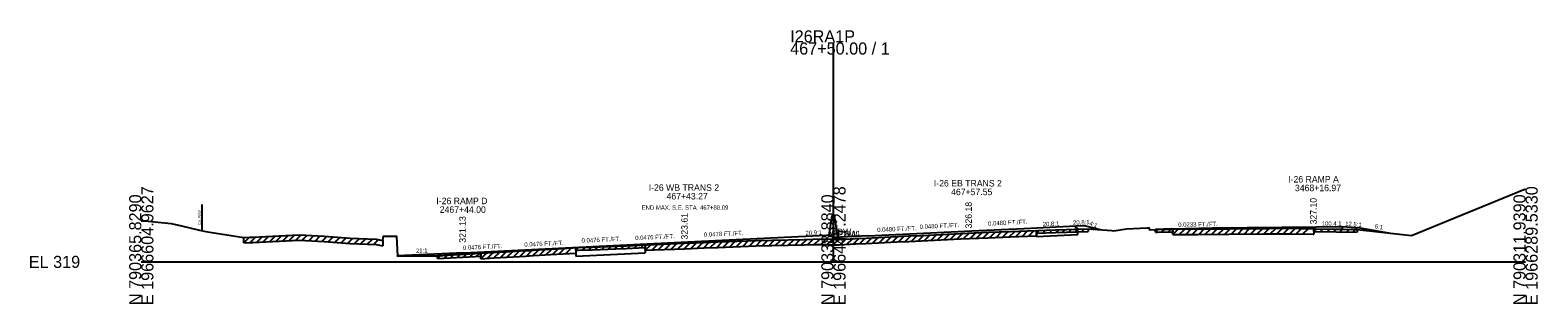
# Model space of a CAD drawing. Extents: x -44 to 4323, y -10 to 9601.
# Drawn here: x 3974.3 to 4322.8, y 5990.3 to 6053.6 of the extents above; entities that cross this region are included whole.
import ezdxf

# ---------------------------------------------------------------- set-up
doc = ezdxf.new("R2010")
doc.units = 0
for name, color, linetype in [('1', 7, 'Continuous'), ('DateStamp', 7, 'Continuous'), ('NotForConst', 7, 'Continuous'), ('QCQA', 7, 'Continuous'), ('RD_SHT_Bndy', 7, 'Continuous'), ('RD_SHT_Iplotshp', 7, 'Continuous'), ('RD_SHT_TX', 7, 'Continuous'), ('RD_XS_ExGround', 7, 'Continuous'), ('RD_XS_MatchLine', 7, 'Continuous'), ('RD_XS_MedBWall', 7, 'Continuous'), ('RD_XS_Misc_Line', 7, 'Continuous'), ('RD_XS_Pave', 7, 'Continuous'), ('RD_XS_PaveOvlay', 7, 'Continuous'), ('RD_XS_PaveShd', 7, 'Continuous'), ('RD_XS_TX_Elev_PR', 7, 'Continuous'), ('RD_XS_TX_Profile', 7, 'Continuous'), ('RD_XS_TX_ShdSlope', 7, 'Continuous'), ('RD_XS_TX_Slope', 7, 'Continuous'), ('seal', 7, 'Continuous'), ('TR SN EXTRUDED PANEL SIGNS - GROUND MOUNTED', 7, 'Continuous')]:
    doc.layers.add(name, color=color, linetype=linetype)

msp = doc.modelspace()

# ---------------------------------------------------------------- linework, layer by layer
at = {"layer": 'DateStamp'}
msp.add_lwpolyline([(4000, 6009.47), (4000.81, 6009.46), (4006.14, 6008.97), (4006.93, 6008.89), (4009.26, 6008.36), (4013.47, 6007.37), (4014.92, 6007.03), (4015.83, 6006.91), (4023.69, 6005.65), (4025.09, 6005.7), (4025.8, 6005.73), (4028.82, 6005.9), (4036.52, 6006.28), (4042.28, 6005.93), (4048.28, 6005.48), (4054.31, 6005.25), (4055.84, 6004.97), (4055.97, 6005.95), (4056.55, 6005.95), (4058.97, 6005.95), (4059.24, 6001.33), (4066.69, 6001.4), (4068.51, 6001.42), (4077.18, 6001.91), (4081.57, 6002.17), (4088.89, 6002.6), (4089.67, 6002.65), (4090.68, 6002.71), (4094.59, 6002.93), (4101.09, 6003.3), (4104.25, 6003.43), (4109.73, 6003.66), (4112.08, 6003.75), (4118.56, 6004.01), (4125.61, 6004.3), (4130.09, 6004.49), (4133.29, 6004.61), (4142.15, 6004.93), (4145.79, 6005.01), (4153.2, 6005.2), (4155.24, 6005.24), (4158.57, 6005.3), (4160.22, 6005.23), (4161.32, 6005.2), (4165.14, 6005.4), (4167.58, 6005.52), (4174.64, 6005.86), (4177.4, 6005.99), (4180.34, 6006.14), (4189.37, 6006.6), (4195.68, 6006.84), (4200.88, 6007.02), (4211.32, 6007.41), (4218.91, 6007.67), (4224.37, 6007.25), (4224.84, 6007.22), (4227.75, 6007.62), (4232.51, 6007.85), (4232.95, 6007.88), (4233.05, 6007.43), (4234.45, 6007.52), (4234.92, 6007.53), (4238.34, 6007.58), (4244.23, 6007.62), (4251.44, 6007.68), (4259.7, 6007.72), (4260.04, 6007.73), (4260.79, 6007.73), (4265.4, 6007.77), (4270.87, 6007.65), (4271.41, 6007.64), (4281.1, 6007.46), (4286.01, 6006.96), (4293.61, 6006.1), (4320, 6016.91)], dxfattribs=at)
at = {"layer": 'NotForConst'}
for p, q in [((4023.69, 6004.4), (4024.99, 6005.7)), ((4025.19, 6004.46), (4026.51, 6005.77)), ((4026.69, 6004.53), (4028.01, 6005.85)), ((4028.19, 6004.61), (4029.51, 6005.93)), ((4029.69, 6004.69), (4031.01, 6006.01)), ((4031.19, 6004.77), (4032.51, 6006.08)), ((4032.69, 6004.84), (4034.01, 6006.16)), ((4034.2, 6004.92), (4035.51, 6006.23)), ((4035.7, 6004.99), (4036.96, 6006.26)), ((4037.2, 6004.99), (4038.38, 6006.17)), ((4038.7, 6004.9), (4039.88, 6006.08)), ((4040.2, 6004.81), (4041.38, 6005.99)), ((4041.7, 6004.72), (4042.87, 6005.89)), ((4043.2, 6004.61), (4044.36, 6005.78)), ((4044.7, 6004.5), (4045.86, 6005.66)), ((4046.2, 6004.39), (4047.36, 6005.55)), ((4047.7, 6004.27), (4048.88, 6005.46)), ((4049.2, 6004.19), (4050.41, 6005.4)), ((4050.7, 6004.14), (4051.91, 6005.34)), ((4052.2, 6004.08), (4053.41, 6005.28)), ((4154.04, 6003.96), (4155.32, 6005.24)), ((4155.54, 6003.99), (4156.82, 6005.27)), ((4157.05, 6004.02), (4158.32, 6005.3)), ((4158.55, 6004.05), (4159.75, 6005.25)), ((4161.55, 6003.96), (4162.87, 6005.28)), ((4163.05, 6004.04), (4164.38, 6005.36)), ((4164.55, 6004.12), (4165.87, 6005.44)), ((4166.06, 6004.2), (4167.37, 6005.51)), ((4167.56, 6004.27), (4168.87, 6005.59)), ((4169.06, 6004.34), (4170.38, 6005.66)), ((4170.56, 6004.42), (4171.88, 6005.73)), ((4172.06, 6004.49), (4173.38, 6005.8)), ((4173.57, 6004.56), (4174.88, 6005.87)), ((4175.07, 6004.63), (4176.38, 6005.95)), ((4176.57, 6004.71), (4177.89, 6006.02)), ((4178.07, 6004.78), (4179.39, 6006.1)), ((4179.57, 6004.86), (4180.89, 6006.17)), ((4181.08, 6004.93), (4182.39, 6006.25)), ((4182.58, 6005.01), (4183.9, 6006.32)), ((4184.08, 6005.08), (4185.4, 6006.4)), ((4185.58, 6005.16), (4186.9, 6006.48)), ((4187.08, 6005.24), (4188.4, 6006.55)), ((4188.58, 6005.31), (4189.9, 6006.62)), ((4190.09, 6005.38), (4191.39, 6006.68)), ((4191.59, 6005.43), (4192.89, 6006.73)), ((4193.09, 6005.49), (4194.39, 6006.79)), ((4194.59, 6005.55), (4195.89, 6006.84)), ((4196.09, 6005.6), (4197.39, 6006.9)), ((4197.6, 6005.65), (4198.89, 6006.95)), ((4199.1, 6005.71), (4200.4, 6007)), ((4200.6, 6005.76), (4201.9, 6007.06)), ((4202.1, 6005.82), (4203.4, 6007.11)), ((4203.6, 6005.87), (4204.9, 6007.17)), ((4205.11, 6005.93), (4206.4, 6007.23)), ((4206.91, 6006.62), (4207.56, 6007.27)), ((4208.41, 6006.67), (4209.06, 6007.32)), ((4209.92, 6006.73), (4210.57, 6007.38)), ((4211.42, 6006.78), (4212.07, 6007.43)), ((4212.92, 6006.84), (4213.57, 6007.48)), ((4214.42, 6006.89), (4215.07, 6007.54)), ((4215.92, 6006.94), (4216.57, 6007.59)), ((4217.43, 6006.99), (4218.07, 6007.64)), ((4234.45, 6006.9), (4235.08, 6007.53)), ((4235.95, 6006.92), (4236.58, 6007.56)), ((4237.45, 6006.95), (4238.09, 6007.58)), ((4238.45, 6006.34), (4239.71, 6007.59)), ((4239.95, 6006.34), (4241.21, 6007.6)), ((4241.45, 6006.35), (4242.71, 6007.61)), ((4242.95, 6006.36), (4244.21, 6007.62)), ((4244.45, 6006.37), (4245.71, 6007.63)), ((4245.96, 6006.39), (4247.22, 6007.65)), ((4247.46, 6006.4), (4248.72, 6007.66)), ((4248.96, 6006.41), (4250.22, 6007.67)), ((4250.46, 6006.42), (4251.72, 6007.68)), ((4251.96, 6006.43), (4253.22, 6007.69)), ((4253.46, 6006.44), (4254.72, 6007.7)), ((4254.97, 6006.45), (4256.22, 6007.71)), ((4256.47, 6006.46), (4257.73, 6007.71)), ((4257.97, 6006.47), (4259.23, 6007.72)), ((4259.47, 6006.47), (4260.73, 6007.73)), ((4260.97, 6006.48), (4262.24, 6007.74)), ((4262.48, 6006.5), (4263.74, 6007.76)), ((4263.98, 6006.51), (4265.24, 6007.77)), ((4265.48, 6006.52), (4266.71, 6007.74)), ((4266.98, 6006.49), (4268.21, 6007.71)), ((4268.48, 6006.46), (4269.71, 6007.68)), ((4271.09, 6007.03), (4271.71, 6007.64)), ((4272.59, 6007), (4273.21, 6007.61)), ((4274.1, 6006.97), (4274.71, 6007.58)), ((4275.6, 6006.94), (4276.21, 6007.56)), ((4277.1, 6006.91), (4277.71, 6007.53)), ((4278.6, 6006.89), (4279.22, 6007.5)), ((4280.1, 6006.86), (4280.72, 6007.47)), ((4053.7, 6004.02), (4054.83, 6005.15)), ((4074.52, 6001.13), (4075.18, 6001.8)), ((4076.02, 6001.22), (4076.68, 6001.88)), ((4077.52, 6001.3), (4078.18, 6001.97)), ((4078.52, 6000.74), (4079.85, 6002.07)), ((4080.02, 6000.83), (4081.35, 6002.16)), ((4081.52, 6000.92), (4082.85, 6002.24)), ((4083.03, 6001.01), (4084.36, 6002.33)), ((4084.53, 6001.09), (4085.86, 6002.42)), ((4086.03, 6001.18), (4087.36, 6002.51)), ((4087.53, 6001.27), (4088.86, 6002.6)), ((4089.03, 6001.36), (4090.36, 6002.69)), ((4090.54, 6001.45), (4091.86, 6002.77)), ((4092.04, 6001.53), (4093.36, 6002.86)), ((4093.54, 6001.62), (4094.87, 6002.95)), ((4095.04, 6001.71), (4096.37, 6003.03)), ((4096.54, 6001.79), (4097.87, 6003.12)), ((4098.04, 6001.88), (4099.37, 6003.2)), ((4100.43, 6002.64), (4101.09, 6003.3)), ((4101.93, 6002.71), (4102.58, 6003.36)), ((4103.43, 6002.77), (4104.09, 6003.43)), ((4104.94, 6002.84), (4105.59, 6003.49)), ((4106.44, 6002.9), (4107.09, 6003.55)), ((4107.94, 6002.96), (4108.59, 6003.61)), ((4109.44, 6003.02), (4110.09, 6003.67)), ((4110.94, 6003.08), (4111.59, 6003.73)), ((4112.44, 6003.14), (4113.1, 6003.79)), ((4113.95, 6003.2), (4114.6, 6003.85)), ((4115.45, 6003.26), (4116.1, 6003.91)), ((4116.49, 6002.68), (4117.8, 6003.98)), ((4118, 6002.74), (4119.3, 6004.04)), ((4119.5, 6002.8), (4120.8, 6004.1)), ((4121, 6002.86), (4122.31, 6004.16)), ((4122.5, 6002.92), (4123.81, 6004.23)), ((4124, 6002.99), (4125.31, 6004.29)), ((4125.51, 6003.05), (4126.81, 6004.35)), ((4127.01, 6003.11), (4128.31, 6004.42)), ((4128.51, 6003.18), (4129.82, 6004.48)), ((4130.01, 6003.24), (4131.31, 6004.54)), ((4131.51, 6003.3), (4132.81, 6004.6)), ((4133.02, 6003.35), (4134.31, 6004.65)), ((4134.52, 6003.41), (4135.81, 6004.7)), ((4136.02, 6003.46), (4137.32, 6004.76)), ((4137.52, 6003.51), (4138.82, 6004.81)), ((4139.02, 6003.57), (4140.32, 6004.86)), ((4140.52, 6003.62), (4141.82, 6004.92)), ((4142.03, 6003.67), (4143.31, 6004.96)), ((4143.53, 6003.71), (4144.81, 6004.99)), ((4145.03, 6003.75), (4146.31, 6005.03)), ((4146.53, 6003.78), (4147.82, 6005.06)), ((4148.03, 6003.82), (4149.32, 6005.1)), ((4149.54, 6003.86), (4150.82, 6005.14)), ((4151.04, 6003.89), (4152.32, 6005.18)), ((4152.54, 6003.93), (4153.82, 6005.21)), ((4160.05, 6003.99), (4161.26, 6005.2)), ((4068.51, 6000.8), (4069.17, 6001.46)), ((4070.01, 6000.88), (4070.67, 6001.54)), ((4071.51, 6000.96), (4072.17, 6001.63)), ((4073.01, 6001.05), (4073.68, 6001.71))]:
    msp.add_line(p, q, dxfattribs=at)
at = {"layer": 'QCQA'}
for p, q in [((4153.2, 6005.2), (4155.24, 6005.24)), ((4155.24, 6005.24), (4158.57, 6005.3)), ((4158.57, 6005.3), (4160.22, 6005.23)), ((4160.22, 6005.23), (4161.32, 6005.2)), ((4161.32, 6005.2), (4165.14, 6005.4)), ((4165.14, 6005.4), (4167.58, 6005.52)), ((4167.58, 6005.52), (4174.64, 6005.86)), ((4174.64, 6005.86), (4177.4, 6005.99)), ((4177.4, 6005.99), (4180.34, 6006.14)), ((4180.34, 6006.14), (4189.37, 6006.6)), ((4189.37, 6006.6), (4195.68, 6006.84)), ((4195.68, 6006.84), (4200.88, 6007.02)), ((4200.88, 6007.02), (4206.91, 6007.24)), ((4238.45, 6007.59), (4234.45, 6007.52)), ((4238.45, 6007.59), (4244.23, 6007.62)), ((4244.23, 6007.62), (4251.44, 6007.68)), ((4251.44, 6007.68), (4259.7, 6007.72)), ((4259.7, 6007.72), (4260.04, 6007.73)), ((4260.04, 6007.73), (4260.79, 6007.73)), ((4260.79, 6007.73), (4265.4, 6007.77)), ((4265.4, 6007.77), (4270.87, 6007.65)), ((4270.87, 6007.65), (4271.09, 6007.65)), ((4271.09, 6007.65), (4277.71, 6007.53)), ((4075.18, 6001.8), (4068.51, 6001.42)), ((4079.38, 6002.04), (4075.18, 6001.8)), ((4088.89, 6002.6), (4079.38, 6002.04)), ((4088.89, 6002.6), (4089.67, 6002.65)), ((4089.67, 6002.65), (4090.68, 6002.71)), ((4100.43, 6003.26), (4090.68, 6002.71)), ((4116.49, 6003.93), (4100.43, 6003.26)), ((4100.43, 6003.26), (4100.43, 6001.33)), ((4116.49, 6003.93), (4118.56, 6004.01)), ((4116.49, 6003.93), (4116.49, 6002.1)), ((4118.56, 6004.01), (4125.61, 6004.3)), ((4125.61, 6004.3), (4130.09, 6004.49)), ((4130.09, 6004.49), (4133.29, 6004.61)), ((4133.29, 6004.61), (4142.15, 6004.93)), ((4142.15, 6004.93), (4145.79, 6005.01)), ((4145.79, 6005.01), (4153.2, 6005.2)), ((4068.51, 6001.42), (4059.24, 6001.33)), ((4059.24, 6001.33), (4059.24, 6001.4))]:
    msp.add_line(p, q, dxfattribs=at)
at = {"layer": 'RD_SHT_Bndy'}
for p, q in [((4160, 6000), (4160, 6050.73)), ((4000, 6000), (4160, 6000)), ((4160, 6000), (4320, 6000))]:
    msp.add_line(p, q, dxfattribs=at)
at = {"layer": 'RD_SHT_Iplotshp'}
for p, q in [((4023.69, 6004.4), (4023.69, 6005.65)), ((4180.34, 6004.89), (4189.37, 6005.35)), ((4189.37, 6005.35), (4195.68, 6005.59)), ((4195.68, 6005.59), (4200.88, 6005.77)), ((4200.88, 6005.77), (4206.91, 6005.99)), ((4206.91, 6007.24), (4206.91, 6005.99)), ((4206.91, 6006.62), (4206.91, 6007.24)), ((4206.91, 6006.62), (4211.32, 6006.78)), ((4211.32, 6006.78), (4218.91, 6007.04)), ((4218.91, 6007.67), (4218.91, 6007.04)), ((4234.45, 6006.9), (4234.45, 6007.52)), ((4234.45, 6006.9), (4234.92, 6006.91)), ((4234.92, 6006.91), (4238.34, 6006.96)), ((4238.34, 6006.96), (4238.45, 6006.96)), ((4238.45, 6006.34), (4238.45, 6007.59)), ((4238.45, 6007.59), (4238.45, 6006.96)), ((4238.45, 6006.34), (4244.23, 6006.37)), ((4244.23, 6006.37), (4251.44, 6006.43)), ((4251.44, 6006.43), (4259.7, 6006.47)), ((4259.7, 6006.47), (4260.04, 6006.48)), ((4260.04, 6006.48), (4260.79, 6006.48)), ((4260.79, 6006.48), (4265.4, 6006.52)), ((4265.4, 6006.52), (4270.87, 6006.4)), ((4270.87, 6006.4), (4271.09, 6006.4)), ((4271.09, 6007.65), (4271.09, 6006.4)), ((4271.09, 6007.03), (4271.09, 6007.65)), ((4271.09, 6007.03), (4271.41, 6007.02)), ((4271.41, 6007.02), (4281.1, 6006.84)), ((4281.1, 6007.46), (4281.1, 6006.84)), ((4023.69, 6004.4), (4025.09, 6004.45)), ((4025.09, 6004.45), (4025.8, 6004.48)), ((4025.8, 6004.48), (4028.82, 6004.65)), ((4028.82, 6004.65), (4036.52, 6005.03)), ((4036.52, 6005.03), (4042.28, 6004.68)), ((4042.28, 6004.68), (4048.28, 6004.23)), ((4048.28, 6004.23), (4054.31, 6004)), ((4054.31, 6004), (4055.84, 6003.72)), ((4055.84, 6004.97), (4055.84, 6003.72)), ((4078.52, 6000.74), (4078.52, 6001.99)), ((4078.52, 6001.99), (4078.52, 6001.36)), ((4094.59, 6001.68), (4100.43, 6002.01)), ((4100.43, 6003.26), (4100.43, 6002.01)), ((4100.43, 6002.64), (4100.43, 6003.26)), ((4100.43, 6002.64), (4101.09, 6002.68)), ((4101.09, 6002.68), (4104.25, 6002.81)), ((4104.25, 6002.81), (4109.73, 6003.03)), ((4109.73, 6003.03), (4112.08, 6003.13)), ((4112.08, 6003.13), (4116.49, 6003.3)), ((4116.49, 6002.68), (4116.49, 6003.93)), ((4116.49, 6003.93), (4116.49, 6003.3)), ((4116.49, 6002.68), (4118.56, 6002.76)), ((4118.56, 6002.76), (4125.61, 6003.05)), ((4125.61, 6003.05), (4130.09, 6003.24)), ((4130.09, 6003.24), (4133.29, 6003.36)), ((4133.29, 6003.36), (4142.15, 6003.68)), ((4142.15, 6003.68), (4145.79, 6003.76)), ((4145.79, 6003.76), (4153.2, 6003.95)), ((4153.2, 6003.95), (4155.24, 6003.99)), ((4155.24, 6003.99), (4158.57, 6004.05)), ((4158.57, 6004.05), (4160.22, 6003.98)), ((4160.22, 6003.98), (4161.32, 6003.95)), ((4161.32, 6003.95), (4165.14, 6004.15)), ((4165.14, 6004.15), (4167.58, 6004.27)), ((4167.58, 6004.27), (4174.64, 6004.61)), ((4174.64, 6004.61), (4177.4, 6004.74)), ((4177.4, 6004.74), (4180.34, 6004.89)), ((4068.51, 6000.8), (4068.51, 6001.42)), ((4068.51, 6000.8), (4077.18, 6001.28)), ((4077.18, 6001.28), (4078.52, 6001.36)), ((4078.52, 6000.74), (4081.57, 6000.92)), ((4081.57, 6000.92), (4088.89, 6001.35)), ((4088.89, 6001.35), (4089.67, 6001.4)), ((4089.67, 6001.4), (4090.68, 6001.46)), ((4090.68, 6001.46), (4094.59, 6001.68))]:
    msp.add_line(p, q, dxfattribs=at)
at = {"layer": 'RD_XS_Misc_Line'}
for p, q in [((4206.91, 6005.86), (4206.91, 6007.24)), ((4206.91, 6005.86), (4216.5, 6006.32)), ((4216, 6007.78), (4216, 6008.34)), ((4216, 6007.78), (4216.5, 6007.8)), ((4216.5, 6006.32), (4216.5, 6007.8)), ((4277.71, 6007.53), (4277.71, 6008.16)), ((4100.43, 6001.33), (4116.49, 6002.1))]:
    msp.add_line(p, q, dxfattribs=at)
at = {"layer": 'RD_XS_Pave'}
for p, q in [((4218, 6008.43), (4222, 6007.43)), ((4281.72, 6007.84), (4289.16, 6006.6))]:
    msp.add_line(p, q, dxfattribs=at)
at = {"layer": 'RD_XS_PaveOvlay'}
msp.add_line((4014, 6013.25), (4014, 6007.25), dxfattribs=at)
at = {"layer": 'RD_XS_PaveShd'}
for p, q in [((4216, 6008.34), (4218, 6008.43)), ((4277.71, 6008.16), (4281.72, 6007.84))]:
    msp.add_line(p, q, dxfattribs=at)
at = {"layer": 'RD_XS_TX_Elev_PR'}
for p, q in [((4150.31, 6005.76), (4160, 6006.22)), ((4160, 6006.22), (4160, 6005.65)), ((4168, 6006.03), (4160, 6005.65)), ((4204, 6007.76), (4216, 6008.34)), ((4238.14, 6007.64), (4234.45, 6007.52)), ((4271.7, 6008.1), (4277.71, 6008.16)), ((4074.59, 6002.13), (4059.24, 6001.4))]:
    msp.add_line(p, q, dxfattribs=at)
at = {"layer": 'RD_XS_TX_ShdSlope'}
for p, q in [((4159, 6006.17), (4159.67, 6010.72)), ((4160.33, 6010.72), (4159.67, 6010.72)), ((4160, 6010.72), (4159.67, 6010.72)), ((4160.33, 6010.15), (4160.33, 6010.72)), ((4161, 6005.7), (4160.33, 6010.15))]:
    msp.add_line(p, q, dxfattribs=at)
at = {"layer": 'RD_XS_TX_Slope'}
for p, q in [((4126.31, 6004.61), (4150.31, 6005.76)), ((4168, 6006.03), (4192, 6007.18)), ((4192, 6007.18), (4204, 6007.76)), ((4238.14, 6007.64), (4247.64, 6007.86)), ((4247.64, 6007.86), (4271.7, 6008.1)), ((4074.59, 6002.13), (4126.31, 6004.61))]:
    msp.add_line(p, q, dxfattribs=at)

# ---------------------------------------------------------------- texts
at = {"layer": '1'}
for s, p in [('I-26 RAMP A', (4265.13, 6018.35)), ('I-26 WB TRANS 2', (4117.3, 6016.43)), ('467+43.27', (4121.42, 6014.43)), ('I-26 EB TRANS 2', (4183.22, 6017.43)), ('467+57.55', (4187.2, 6015.43)), ('3468+16.97', (4266.69, 6016.35)), ('I-26 RAMP D', (4068.21, 6013.34)), ('2467+44.00', (4068.99, 6011.34))]:
    msp.add_text(s, height=1.5, dxfattribs=at).set_placement(p)
at = {"layer": 'RD_SHT_Bndy'}
for s, p in [('467+50.00 / 1', (4150, 6047.93)), ('I26RA1P', (4150, 6050.73)), ('EL 319', (3974, 5998.6))]:
    msp.add_text(s, height=2.8, dxfattribs=at).set_placement(p)
for s, p in [('E 1966604.9627', (4002.8, 5990)), ('E 1966447.2478', (4162.8, 5990)), ('E 1966289.5330', (4322.8, 5990)), ('N 790365.8290', (4000, 5990)), ('N 790338.8840', (4160, 5990)), ('N 790311.9390', (4320, 5990))]:
    msp.add_text(s, height=2.8, rotation=90, dxfattribs=at).set_placement(p)
at = {"layer": 'RD_SHT_TX'}
msp.add_text('324.24', height=1, rotation=90, dxfattribs=at).set_placement((4161, 6005.24))
at = {"layer": 'RD_XS_ExGround'}
for s, rotation, p in [('20.8:1', 2.7481, (4208.41, 6008.22)), ('20.9:1', 2.7384, (4153.57, 6006.16)), ('20.8:1', 2.7481, (4162.41, 6006.01)), ('21:1', 2.7234, (4063.51, 6002.05))]:
    msp.add_text(s, height=1, rotation=rotation, dxfattribs=at).set_placement(p)
at = {"layer": 'RD_XS_MatchLine'}
msp.add_text('END MAX. S.E. STA. 467+88.09', height=1, dxfattribs=at).set_placement((4115.65, 6012.05))
at = {"layer": 'RD_XS_MedBWall'}
for s, rotation, p in [('20.8:1', 2.7481, (4215.41, 6008.56)), ('12.5:1', 355.4336, (4278.26, 6008.37))]:
    msp.add_text(s, height=1, rotation=rotation, dxfattribs=at).set_placement(p)
at = {"layer": 'RD_XS_PaveOvlay'}
msp.add_text('Ex. R/W ', height=0.65, rotation=90, dxfattribs=at).set_placement((4013.75, 6008.63))
at = {"layer": 'RD_XS_TX_Profile'}
for s, p in [('WBW', (4159, 6006.17)), ('EBW', (4161, 6005.7))]:
    msp.add_text(s, height=1.5, dxfattribs=at).set_placement(p)
at = {"layer": 'seal'}
for s, p in [(' 326.18', (4192, 6007.18)), (' 327.10', (4271.7, 6008.1)), ('321.13', (4075, 6004.43)), (' 323.61', (4126.31, 6004.61))]:
    msp.add_text(s, height=1.5, rotation=90, dxfattribs=at).set_placement(p)
at = {"layer": 'TR SN EXTRUDED PANEL SIGNS - GROUND MOUNTED'}
for s, rotation, p in [('0.0480 FT./FT.', 2.7481, (4179.95, 6007.61)), ('0.0480 FT./FT.', 2.7481, (4195.77, 6008.37)), ('4:1', 340.9653, (4219.04, 6008.5)), ('0.0233 FT./FT.', 1.3331, (4239.71, 6008.09)), ('100.4:1', 0.5706, (4272.88, 6008.36)), ('6:1', 350.553, (4285.11, 6007.79)), ('0.0476 FT./FT.', 2.7234, (4101.8, 6004.42)), ('0.0476 FT./FT.', 2.7234, (4114.2, 6005.03)), ('0.0478 FT./FT.', 2.7384, (4130.08, 6005.79)), ('0.0480 FT./FT.', 2.7481, (4170.14, 6006.89)), ('0.0476 FT./FT.', 2.7234, (4074.37, 6002.75)), ('0.0476 FT./FT.', 2.7234, (4088.56, 6003.5))]:
    msp.add_text(s, height=1, rotation=rotation, dxfattribs=at).set_placement(p)

doc.saveas('drawing.dxf')
